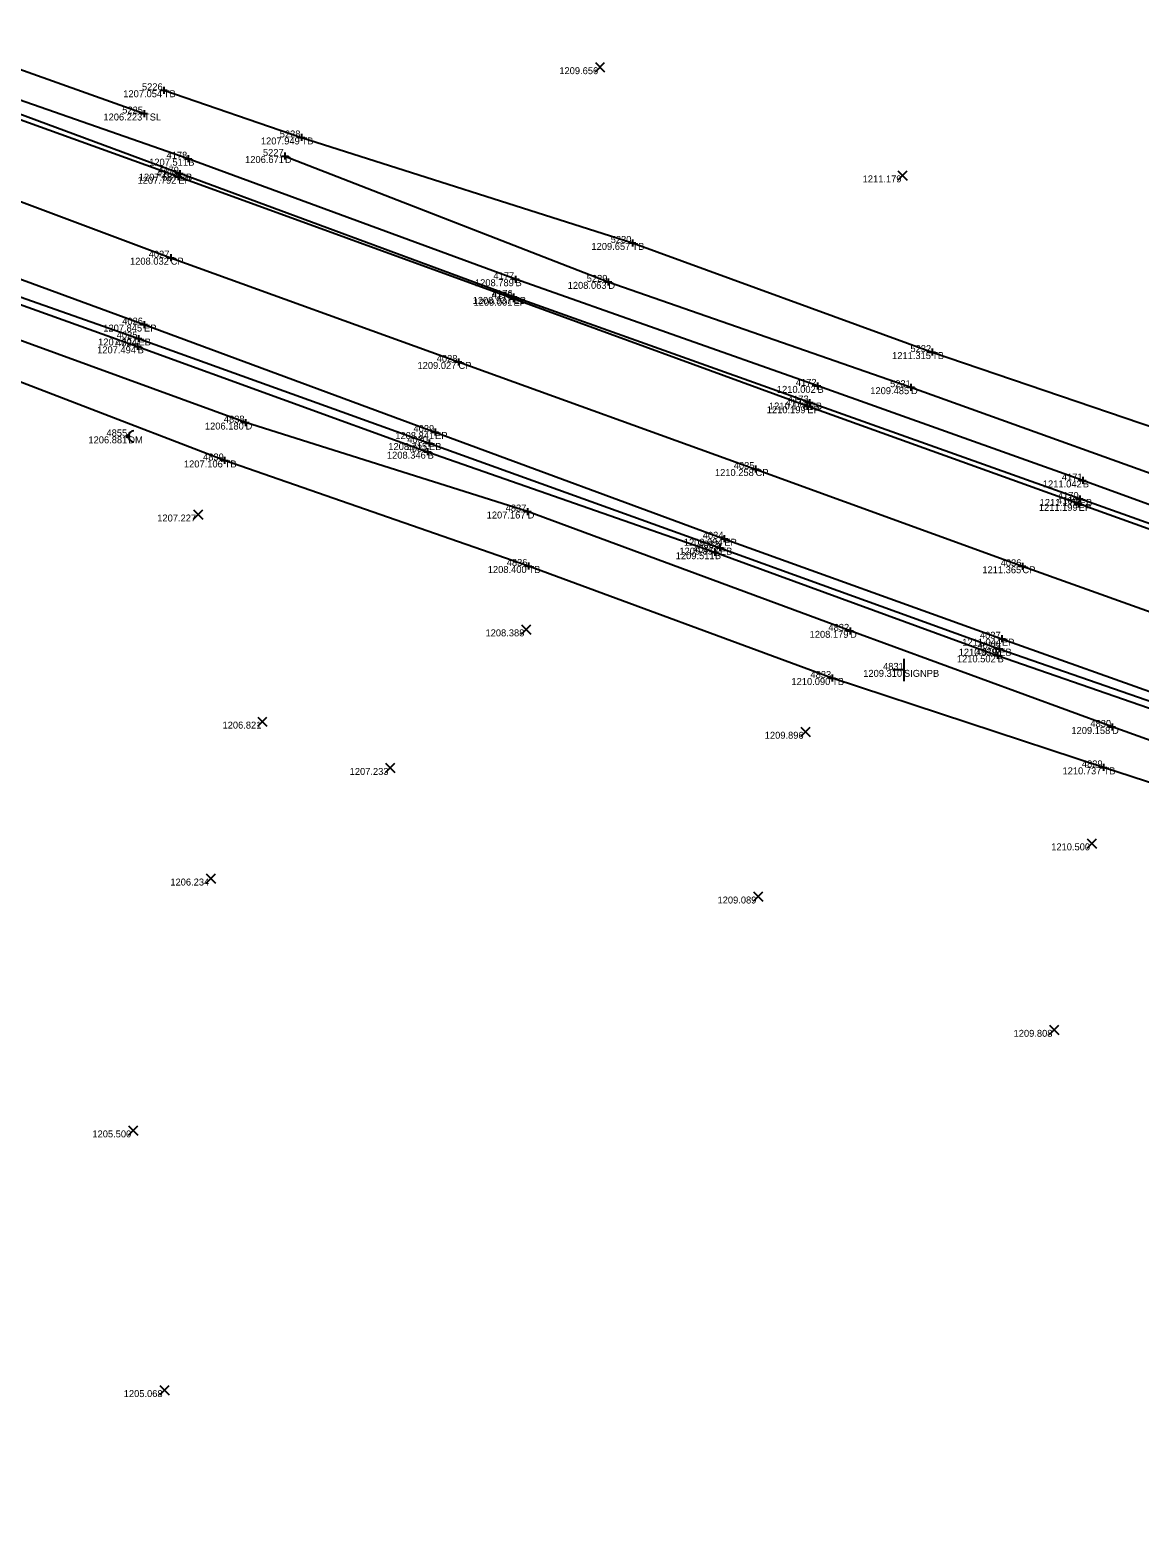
# Model space of a CAD drawing. Extents: x 2044996 to 2050343, y 455232 to 458054.
# Drawn here: x 2047743.9 to 2047903.2, y 456761.8 to 456978.2 of the extents above; entities that cross this region are included whole.
import ezdxf

# ---------------------------------------------------------------- set-up
doc = ezdxf.new("R2010")
doc.units = 0
for name, color, linetype in [('DR_X_Ditch', 7, 'Continuous'), ('DT_X_Contour_Minor', 7, 'Continuous'), ('DT_X_Contour_Text', 7, 'Continuous'), ('DT_X_Island', 7, 'Continuous'), ('DT_X_Spot_Elev', 7, 'Continuous'), ('DT_X_Triangles', 7, 'Continuous'), ('DT_X_Void', 7, 'Continuous'), ('PV_X_COP', 7, 'Continuous'), ('PV_X_EOP', 7, 'Continuous'), ('PV_X_Shoulder_Aggregate', 7, 'Continuous'), ('SN_X_Public', 7, 'Continuous'), ('SV_X_Break_Lines', 7, 'Continuous'), ('SV_X_Toe_of_Slope', 7, 'Continuous'), ('SV_X_Top_of_Bank', 7, 'Continuous')]:
    doc.layers.add(name, color=color, linetype=linetype)

msp = doc.modelspace()

# ---------------------------------------------------------------- linework, layer by layer
at = {"layer": 'DR_X_Ditch'}
for points in [[(2047780.51, 456960.13), (2047826.93, 456942.06), (2047870.38, 456926.94), (2047917.77, 456909.91), (2047942.94, 456900.89), (2047986.92, 456884.17), (2048032.77, 456867.49), (2048075.71, 456852.37), (2048118.48, 456836.63), (2048162.27, 456821), (2048204.38, 456806.34), (2048252.02, 456790.17), (2048298.22, 456772.41), (2048313.77, 456769.57), (2048332, 456765.35)], [(2047944.96, 456861.76), (2047899.25, 456878.16), (2047861.64, 456891.96), (2047815.35, 456909.09), (2047774.86, 456921.86), (2047729.93, 456938.25), (2047691.42, 456950.76), (2047669.22, 456956.37), (2047658.75, 456950.98), (2047651.4, 456909.49), (2047651.98, 456861.4), (2047653.43, 456816.89), (2047656.94, 456761.43), (2047657.83, 456718.94), (2047659.36, 456677.43), (2047660.77, 456628.12), (2047661.37, 456577.1), (2047662.68, 456519.59), (2047665.25, 456466.46), (2047666.16, 456418.54), (2047665.56, 456406.95)]]:
    msp.add_lwpolyline(points, dxfattribs=at)
at = {"layer": 'DT_X_Island'}
msp.add_circle((2047758.02, 456919.88), 0.2, dxfattribs=at)
msp.add_arc((2047758.82, 456919.88), 0.8, 90, 270, dxfattribs=at)
at = {"layer": 'DT_X_Spot_Elev'}
for p, q in [((2047825.07, 456972.21), (2047826.4, 456973.54)), ((2047825.07, 456973.54), (2047826.4, 456972.21)), ((2047868.49, 456956.67), (2047869.82, 456958.01)), ((2047868.49, 456958.01), (2047869.82, 456956.67)), ((2047767.4, 456907.99), (2047768.73, 456909.33)), ((2047767.4, 456909.33), (2047768.73, 456907.99)), ((2047814.47, 456891.5), (2047815.8, 456892.83)), ((2047814.47, 456892.83), (2047815.8, 456891.5)), ((2047776.6, 456878.26), (2047777.93, 456879.59)), ((2047776.6, 456879.59), (2047777.93, 456878.26)), ((2047854.56, 456876.8), (2047855.89, 456878.13)), ((2047854.56, 456878.13), (2047855.89, 456876.8)), ((2047794.96, 456871.61), (2047796.29, 456872.95)), ((2047794.96, 456872.95), (2047796.29, 456871.61)), ((2047895.68, 456860.78), (2047897.01, 456862.11)), ((2047895.68, 456862.11), (2047897.01, 456860.78)), ((2047769.2, 456855.73), (2047770.54, 456857.07)), ((2047769.2, 456857.07), (2047770.54, 456855.73)), ((2047847.76, 456853.16), (2047849.09, 456854.49)), ((2047847.76, 456854.49), (2047849.09, 456853.16)), ((2047890.28, 456834.01), (2047891.61, 456835.35)), ((2047890.28, 456835.35), (2047891.61, 456834.01)), ((2047758.04, 456819.57), (2047759.37, 456820.9)), ((2047758.04, 456820.9), (2047759.37, 456819.57)), ((2047762.54, 456782.3), (2047763.87, 456783.63)), ((2047762.54, 456783.63), (2047763.87, 456782.3))]:
    msp.add_line(p, q, dxfattribs=at)
at = {"layer": 'DT_X_Void'}
for p, q in [((2047763.11, 456970.07), (2047763.11, 456969.07)), ((2047762.61, 456969.57), (2047763.61, 456969.57)), ((2047763.11, 456969.57), (2047763.11, 456969.57)), ((2047759.78, 456966.23), (2047760.78, 456966.23)), ((2047760.28, 456966.73), (2047760.28, 456965.73)), ((2047760.28, 456966.23), (2047760.28, 456966.23)), ((2047782.38, 456962.79), (2047783.38, 456962.79)), ((2047782.88, 456963.29), (2047782.88, 456962.29)), ((2047782.88, 456962.79), (2047782.88, 456962.79)), ((2047766.13, 456959.74), (2047767.13, 456959.74)), ((2047766.63, 456960.24), (2047766.63, 456959.24)), ((2047766.63, 456959.74), (2047766.63, 456959.74)), ((2047780.01, 456960.13), (2047781.01, 456960.13)), ((2047780.51, 456960.63), (2047780.51, 456959.63)), ((2047780.51, 456960.13), (2047780.51, 456960.13)), ((2047764.69, 456957.15), (2047765.69, 456957.15)), ((2047764.91, 456957.6), (2047765.91, 456957.6)), ((2047765.19, 456957.65), (2047765.19, 456956.65)), ((2047765.19, 456957.15), (2047765.19, 456957.15)), ((2047765.41, 456958.1), (2047765.41, 456957.1)), ((2047765.41, 456957.6), (2047765.41, 456957.6)), ((2047829.89, 456947.65), (2047830.89, 456947.65)), ((2047830.39, 456948.15), (2047830.39, 456947.15)), ((2047830.39, 456947.65), (2047830.39, 456947.65)), ((2047763.61, 456945.53), (2047764.61, 456945.53)), ((2047764.11, 456946.03), (2047764.11, 456945.03)), ((2047764.11, 456945.53), (2047764.11, 456945.53)), ((2047813.11, 456942.44), (2047814.11, 456942.44)), ((2047813.61, 456942.94), (2047813.61, 456941.94)), ((2047813.61, 456942.44), (2047813.61, 456942.44)), ((2047826.43, 456942.06), (2047827.43, 456942.06)), ((2047826.93, 456942.56), (2047826.93, 456941.56)), ((2047826.93, 456942.06), (2047826.93, 456942.06)), ((2047812.81, 456939.64), (2047813.81, 456939.64)), ((2047812.84, 456939.9), (2047813.84, 456939.9)), ((2047813.31, 456940.14), (2047813.31, 456939.14)), ((2047813.31, 456939.64), (2047813.31, 456939.64)), ((2047813.34, 456940.4), (2047813.34, 456939.4)), ((2047813.34, 456939.9), (2047813.34, 456939.9)), ((2047759.78, 456935.93), (2047760.78, 456935.93)), ((2047760.28, 456936.43), (2047760.28, 456935.43)), ((2047760.28, 456935.93), (2047760.28, 456935.93)), ((2047758.99, 456933.93), (2047759.99, 456933.93)), ((2047759.36, 456933.3), (2047759.36, 456932.3)), ((2047759.49, 456934.43), (2047759.49, 456933.43)), ((2047759.49, 456933.93), (2047759.49, 456933.93)), ((2047758.86, 456932.8), (2047759.86, 456932.8)), ((2047759.36, 456932.8), (2047759.36, 456932.8)), ((2047805.42, 456931.06), (2047805.42, 456930.06)), ((2047872.91, 456931.98), (2047873.91, 456931.98)), ((2047873.41, 456932.48), (2047873.41, 456931.48)), ((2047873.41, 456931.98), (2047873.41, 456931.98)), ((2047804.92, 456930.56), (2047805.92, 456930.56)), ((2047805.42, 456930.56), (2047805.42, 456930.56)), ((2047856.46, 456927.13), (2047857.46, 456927.13)), ((2047856.96, 456927.63), (2047856.96, 456926.63)), ((2047856.96, 456927.13), (2047856.96, 456927.13)), ((2047869.88, 456926.94), (2047870.88, 456926.94)), ((2047870.38, 456927.44), (2047870.38, 456926.44)), ((2047870.38, 456926.94), (2047870.38, 456926.94)), ((2047855.33, 456924.74), (2047856.33, 456924.74)), ((2047855.5, 456924.7), (2047855.5, 456923.7)), ((2047855.83, 456925.24), (2047855.83, 456924.24)), ((2047855.83, 456924.74), (2047855.83, 456924.74)), ((2047774.86, 456922.36), (2047774.86, 456921.36)), ((2047855, 456924.2), (2047856, 456924.2)), ((2047855.5, 456924.2), (2047855.5, 456924.2)), ((2047774.36, 456921.86), (2047775.36, 456921.86)), ((2047774.86, 456921.86), (2047774.86, 456921.86)), ((2047801.56, 456920.5), (2047802.56, 456920.5)), ((2047802.06, 456921), (2047802.06, 456920)), ((2047802.06, 456920.5), (2047802.06, 456920.5)), ((2047800.69, 456918.92), (2047801.69, 456918.92)), ((2047800.99, 456918.18), (2047800.99, 456917.18)), ((2047801.19, 456919.42), (2047801.19, 456918.42)), ((2047801.19, 456918.92), (2047801.19, 456918.92)), ((2047771.35, 456916.42), (2047772.35, 456916.42)), ((2047771.85, 456916.92), (2047771.85, 456915.92)), ((2047771.85, 456916.42), (2047771.85, 456916.42)), ((2047800.49, 456917.68), (2047801.49, 456917.68)), ((2047800.99, 456917.68), (2047800.99, 456917.68)), ((2047847.57, 456915.19), (2047848.57, 456915.19)), ((2047848.07, 456915.69), (2047848.07, 456914.69)), ((2047848.07, 456915.19), (2047848.07, 456915.19)), ((2047895.04, 456914.05), (2047895.04, 456913.05)), ((2047894.54, 456913.55), (2047895.54, 456913.55)), ((2047895.04, 456913.55), (2047895.04, 456913.55)), ((2047815.35, 456909.59), (2047815.35, 456908.59)), ((2047893.95, 456910.18), (2047894.95, 456910.18)), ((2047894.1, 456910.89), (2047895.1, 456910.89)), ((2047894.45, 456910.68), (2047894.45, 456909.68)), ((2047894.45, 456910.18), (2047894.45, 456910.18)), ((2047894.6, 456911.39), (2047894.6, 456910.39)), ((2047894.6, 456910.89), (2047894.6, 456910.89)), ((2047814.85, 456909.09), (2047815.85, 456909.09)), ((2047815.35, 456909.09), (2047815.35, 456909.09)), ((2047843.08, 456905.18), (2047844.08, 456905.18)), ((2047843.58, 456905.68), (2047843.58, 456904.68)), ((2047843.58, 456905.18), (2047843.58, 456905.18)), ((2047841.73, 456903.25), (2047842.73, 456903.25)), ((2047842.23, 456903.75), (2047842.23, 456902.75)), ((2047842.23, 456903.25), (2047842.23, 456903.25)), ((2047842.46, 456903.9), (2047843.46, 456903.9)), ((2047842.96, 456904.4), (2047842.96, 456903.4)), ((2047842.96, 456903.9), (2047842.96, 456903.9)), ((2047814.97, 456901.27), (2047815.97, 456901.27)), ((2047815.47, 456901.77), (2047815.47, 456900.77)), ((2047815.47, 456901.27), (2047815.47, 456901.27)), ((2047885.88, 456901.23), (2047886.88, 456901.23)), ((2047886.38, 456901.73), (2047886.38, 456900.73)), ((2047886.38, 456901.23), (2047886.38, 456901.23)), ((2047861.64, 456892.46), (2047861.64, 456891.46)), ((2047861.14, 456891.96), (2047862.14, 456891.96)), ((2047861.64, 456891.96), (2047861.64, 456891.96)), ((2047882.94, 456890.83), (2047883.94, 456890.83)), ((2047883.05, 456889.9), (2047883.05, 456888.9)), ((2047883.44, 456891.33), (2047883.44, 456890.33)), ((2047883.44, 456890.83), (2047883.44, 456890.83)), ((2047882.31, 456888.44), (2047883.31, 456888.44)), ((2047882.55, 456889.4), (2047883.55, 456889.4)), ((2047882.81, 456888.94), (2047882.81, 456887.94)), ((2047882.81, 456888.44), (2047882.81, 456888.44)), ((2047883.05, 456889.4), (2047883.05, 456889.4)), ((2047859.06, 456885.69), (2047859.06, 456884.69)), ((2047858.56, 456885.19), (2047859.56, 456885.19)), ((2047859.06, 456885.19), (2047859.06, 456885.19)), ((2047898.75, 456878.16), (2047899.75, 456878.16)), ((2047899.25, 456878.66), (2047899.25, 456877.66)), ((2047899.25, 456878.16), (2047899.25, 456878.16)), ((2047898.01, 456872.86), (2047898.01, 456871.86)), ((2047897.51, 456872.36), (2047898.51, 456872.36)), ((2047898.01, 456872.36), (2047898.01, 456872.36))]:
    msp.add_line(p, q, dxfattribs=at)
at = {"layer": 'PV_X_COP'}
msp.add_lwpolyline([(2047721.58, 456961.45), (2047764.11, 456945.53), (2047805.42, 456930.56), (2047848.07, 456915.19), (2047886.38, 456901.23), (2047928.53, 456886.16), (2047967.24, 456872.35), (2048004.2, 456859.18), (2048043.3, 456845.25), (2048086.02, 456829.64), (2048125.99, 456815.39), (2048168.62, 456799.78), (2048207.67, 456785.38), (2048251.12, 456769.74), (2048292.61, 456754.36), (2048333.81, 456739.22), (2048373.81, 456724.48), (2048417.09, 456709.08), (2048458.61, 456693.82), (2048498.86, 456678.79), (2048537.43, 456664.8), (2048579.13, 456649.5), (2048615.78, 456636.27)], dxfattribs=at)
at = {"layer": 'PV_X_EOP'}
for p, q in [((2047765.19, 456957.15), (2047718.53, 456973.97)), ((2047813.31, 456939.64), (2047765.19, 456957.15)), ((2047719.82, 456950.78), (2047760.28, 456935.93)), ((2047855.5, 456924.2), (2047813.31, 456939.64)), ((2047760.28, 456935.93), (2047802.06, 456920.5)), ((2047894.45, 456910.18), (2047855.5, 456924.2)), ((2047802.06, 456920.5), (2047843.58, 456905.18)), ((2047937.77, 456894.62), (2047894.45, 456910.18)), ((2047843.58, 456905.18), (2047883.44, 456890.83)), ((2047883.44, 456890.83), (2047924.52, 456876.14))]:
    msp.add_line(p, q, dxfattribs=at)
at = {"layer": 'PV_X_Shoulder_Aggregate'}
for points in [[(2048620.54, 456647.12), (2048583.12, 456660.67), (2048539.73, 456676.45), (2048498.23, 456691.52), (2048454.17, 456707.97), (2048410.24, 456724.1), (2048369.4, 456738.65), (2048329.21, 456753.43), (2048288.45, 456768.21), (2048244.06, 456784.69), (2048200.54, 456800.78), (2048154.81, 456817.47), (2048112.55, 456832.71), (2048067.31, 456849.18), (2048026.51, 456863.76), (2047982.25, 456879.67), (2047938.09, 456895.41), (2047894.6, 456910.89), (2047855.83, 456924.74), (2047813.34, 456939.9), (2047765.41, 456957.6), (2047718.77, 456974.89)], [(2047718.66, 456948.27), (2047759.49, 456933.93), (2047801.19, 456918.92), (2047842.96, 456903.9), (2047883.05, 456889.4), (2047924.02, 456875.18), (2047951.15, 456865.01), (2047953.56, 456863.19), (2047959.99, 456860.81), (2047979.02, 456853.88), (2047983.62, 456853.54), (2047999.27, 456848.34), (2048040.39, 456833.65), (2048080.57, 456819.36)]]:
    msp.add_lwpolyline(points, dxfattribs=at)
at = {"layer": 'SN_X_Public'}
for p, q in [((2047869.37, 456887.96), (2047869.37, 456884.76)), ((2047869.37, 456886.36), (2047867.77, 456886.36))]:
    msp.add_line(p, q, dxfattribs=at)
at = {"layer": 'SV_X_Break_Lines'}
for points in [[(2048620.73, 456648.35), (2048583.39, 456661.98), (2048539.9, 456677.65), (2048498.37, 456692.73), (2048454.2, 456708.99), (2048410.48, 456724.96), (2048370.07, 456739.9), (2048329.65, 456754.5), (2048288.87, 456769.18), (2048244.36, 456785.65), (2048200.73, 456801.81), (2048154.72, 456818.61), (2048112.67, 456833.97), (2048067.63, 456850.21), (2048026.62, 456865.12), (2047982.64, 456881.49), (2047938.6, 456897.69), (2047895.04, 456913.55), (2047856.96, 456927.13), (2047813.61, 456942.44), (2047766.63, 456959.74), (2047718.99, 456976.33)], [(2047652.8, 456955.87), (2047664.54, 456962.83), (2047671.52, 456961.88), (2047676.87, 456960.65), (2047718.46, 456947.45), (2047759.36, 456932.8), (2047800.99, 456917.68), (2047842.23, 456903.25), (2047882.81, 456888.44), (2047923.67, 456874.28), (2047947.96, 456864.48)]]:
    msp.add_lwpolyline(points, dxfattribs=at)
at = {"layer": 'SV_X_Toe_of_Slope'}
msp.add_lwpolyline([(2047656.35, 457022.83), (2047660.05, 457013.16), (2047664.41, 457005.04), (2047675.76, 456997.03), (2047717.96, 456981.3), (2047760.28, 456966.23)], dxfattribs=at)
at = {"layer": 'SV_X_Top_of_Bank'}
for points in [[(2047763.11, 456969.57), (2047782.88, 456962.79), (2047830.39, 456947.65), (2047873.41, 456931.98), (2047921.78, 456915.49), (2047944.39, 456907.04), (2047986.44, 456890.77), (2048035.77, 456871.04), (2048076.02, 456855.86), (2048121.82, 456840.13), (2048161.94, 456823.83), (2048204.58, 456808.51), (2048251.96, 456791.72), (2048298.91, 456775.05), (2048316.55, 456773.31), (2048328.45, 456771.26), (2048326.74, 456784.97)], [(2047942.14, 456857.99), (2047898.01, 456872.36), (2047859.06, 456885.19), (2047815.47, 456901.27), (2047771.85, 456916.42), (2047729.97, 456932.49), (2047688.22, 456947.3), (2047669.99, 456955.17), (2047661.07, 456948.62), (2047656.72, 456911.9), (2047659.76, 456864.17), (2047662.28, 456815.7), (2047662.72, 456763.39), (2047662.48, 456719.38), (2047665.2, 456677.14), (2047665.7, 456629.87), (2047667.28, 456578.15), (2047668.69, 456520.88), (2047669.88, 456466.8), (2047671, 456408.28)]]:
    msp.add_lwpolyline(points, dxfattribs=at)

# ---------------------------------------------------------------- texts
at = {"layer": 'DT_X_Contour_Minor'}
for s, p in [('1209.656', (2047819.9, 456971.88)), ('1207.054', (2047757.3, 456968.57)), ('1206.223', (2047754.45, 456965.23)), ('1207.949', (2047777.06, 456961.79)), ('1207.511', (2047761.02, 456958.74)), ('1206.671', (2047774.79, 456959.13)), ('1207.792', (2047759.35, 456956.15)), ('1207.687', (2047759.53, 456956.6)), ('1211.179', (2047863.44, 456956.34)), ('1209.657', (2047824.51, 456946.65)), ('1208.032', (2047758.27, 456944.53)), ('1208.789', (2047807.79, 456941.44)), ('1208.063', (2047821.1, 456941.06)), ('1208.937', (2047807.46, 456938.9)), ('1209.001', (2047807.59, 456938.64)), ('1207.845', (2047754.43, 456934.93)), ('1207.704', (2047753.69, 456932.93)), ('1207.494', (2047753.55, 456931.8)), ('1211.315', (2047867.67, 456930.98)), ('1209.027', (2047799.54, 456929.56)), ('1210.002', (2047851.13, 456926.13)), ('1209.485', (2047864.54, 456925.94)), ('1210.178', (2047849.99, 456923.74)), ('1210.199', (2047849.68, 456923.2)), ('1206.180', (2047769.02, 456920.86)), ('1208.841', (2047796.35, 456919.5)), ('1206.881', (2047752.3, 456918.88)), ('1208.715', (2047795.35, 456917.92)), ('1207.106', (2047766.01, 456915.42)), ('1208.346', (2047795.15, 456916.68)), ('1210.258', (2047842.24, 456914.19)), ('1211.042', (2047889.31, 456912.55)), ('1211.199', (2047888.73, 456909.18)), ('1211.175', (2047888.85, 456909.89)), ('1207.227', (2047762.18, 456907.66)), ('1207.167', (2047809.47, 456908.09)), ('1209.994', (2047837.77, 456904.18)), ('1209.511', (2047836.61, 456902.25)), ('1209.853', (2047837.13, 456902.9)), ('1208.400', (2047809.63, 456900.27)), ('1211.365', (2047880.63, 456900.23)), ('1208.388', (2047809.3, 456891.17)), ('1208.179', (2047855.83, 456890.96)), ('1211.044', (2047877.74, 456889.83)), ('1210.502', (2047876.97, 456887.44)), ('1210.919', (2047877.23, 456888.4)), ('1209.310', (2047863.53, 456885.36)), ('1210.090', (2047853.22, 456884.19)), ('1206.821', (2047771.55, 456877.93)), ('1209.896', (2047849.39, 456876.47)), ('1209.158', (2047893.41, 456877.16)), ('1207.233', (2047789.8, 456871.28)), ('1210.737', (2047892.13, 456871.36)), ('1210.500', (2047890.51, 456860.45)), ('1206.234', (2047764.06, 456855.4)), ('1209.089', (2047842.61, 456852.82)), ('1209.808', (2047885.11, 456833.68)), ('1205.500', (2047752.87, 456819.24)), ('1205.068', (2047757.37, 456781.96))]:
    msp.add_text(s, height=1, dxfattribs=at).set_placement(p)
at = {"layer": 'DT_X_Contour_Text'}
for s, p in [('TB', (2047763.11, 456968.57)), ('TSL', (2047760.28, 456965.23)), ('TB', (2047782.88, 456961.79)), ('B', (2047766.63, 456958.74)), ('D', (2047780.51, 456959.13)), ('EP', (2047765.19, 456956.15)), ('EB', (2047765.41, 456956.6)), ('TB', (2047830.39, 456946.65)), ('CP', (2047764.11, 456944.53)), ('B', (2047813.61, 456941.44)), ('D', (2047826.93, 456941.06)), ('EP', (2047813.31, 456938.64)), ('EB', (2047813.34, 456938.9)), ('EP', (2047760.28, 456934.93)), ('EB', (2047759.49, 456932.93)), ('B', (2047759.36, 456931.8)), ('TB', (2047873.41, 456930.98)), ('CP', (2047805.42, 456929.56)), ('B', (2047856.96, 456926.13)), ('D', (2047870.38, 456925.94)), ('EB', (2047855.83, 456923.74)), ('EP', (2047855.5, 456923.2)), ('D', (2047774.86, 456920.86)), ('EP', (2047802.06, 456919.5)), ('DM', (2047758.02, 456918.88)), ('EB', (2047801.19, 456917.92)), ('TB', (2047771.85, 456915.42)), ('B', (2047800.99, 456916.68)), ('CP', (2047848.07, 456914.19)), ('B', (2047895.04, 456912.55)), ('EP', (2047894.45, 456909.18)), ('EB', (2047894.6, 456909.89)), ('D', (2047815.35, 456908.09)), ('EP', (2047843.58, 456904.18)), ('B', (2047842.23, 456902.25)), ('EB', (2047842.96, 456902.9)), ('TB', (2047815.47, 456900.27)), ('CP', (2047886.38, 456900.23)), ('D', (2047861.64, 456890.96)), ('EP', (2047883.44, 456889.83)), ('B', (2047882.81, 456887.44)), ('EB', (2047883.05, 456888.4)), ('SIGNPB', (2047869.37, 456885.36)), ('TB', (2047859.06, 456884.19)), ('D', (2047899.25, 456877.16)), ('TB', (2047898.01, 456871.36))]:
    msp.add_text(s, height=1, dxfattribs=at).set_placement(p)
at = {"layer": 'DT_X_Triangles'}
for s, p in [('5226', (2047759.98, 456969.57)), ('5225', (2047757.15, 456966.23)), ('5228', (2047779.76, 456962.79)), ('4178', (2047763.51, 456959.74)), ('5227', (2047777.35, 456960.13)), ('4180', (2047762.07, 456957.15)), ('4179', (2047762.31, 456957.6)), ('5230', (2047827.27, 456947.65)), ('4027', (2047760.95, 456945.53)), ('4177', (2047810.44, 456942.44)), ('5229', (2047823.83, 456942.06)), ('4175', (2047810.18, 456939.64)), ('4176', (2047810.22, 456939.9)), ('4026', (2047757.15, 456935.93)), ('4024', (2047756.27, 456932.8)), ('4025', (2047756.36, 456933.93)), ('4028', (2047802.3, 456930.56)), ('5232', (2047870.3, 456931.98)), ('4172', (2047853.85, 456927.13)), ('5231', (2047867.38, 456926.94)), ('4174', (2047852.41, 456924.2)), ('4173', (2047852.72, 456924.74)), ('4838', (2047771.74, 456921.86)), ('4855', (2047754.89, 456919.88)), ('4029', (2047798.96, 456920.5)), ('4031', (2047797.99, 456917.68)), ('4030', (2047798.07, 456918.92)), ('4839', (2047768.76, 456916.42)), ('4035', (2047844.94, 456915.19)), ('4171', (2047892.04, 456913.55)), ('4170', (2047891.48, 456910.89)), ('4837', (2047812.19, 456909.09)), ('4169', (2047891.35, 456910.18)), ('4034', (2047840.49, 456905.18)), ('4032', (2047839.11, 456903.25)), ('4033', (2047839.85, 456903.9)), ('4836', (2047812.35, 456901.27)), ('4036', (2047883.26, 456901.23)), ('4832', (2047858.53, 456891.96)), ('4038', (2047879.93, 456889.4)), ('4037', (2047880.28, 456890.83)), ('4039', (2047879.71, 456888.44)), ('4833', (2047855.95, 456885.19)), ('4831', (2047866.37, 456886.36)), ('4830', (2047896.13, 456878.16)), ('4829', (2047894.91, 456872.36))]:
    msp.add_text(s, height=1, dxfattribs=at).set_placement(p)

doc.saveas('drawing.dxf')
